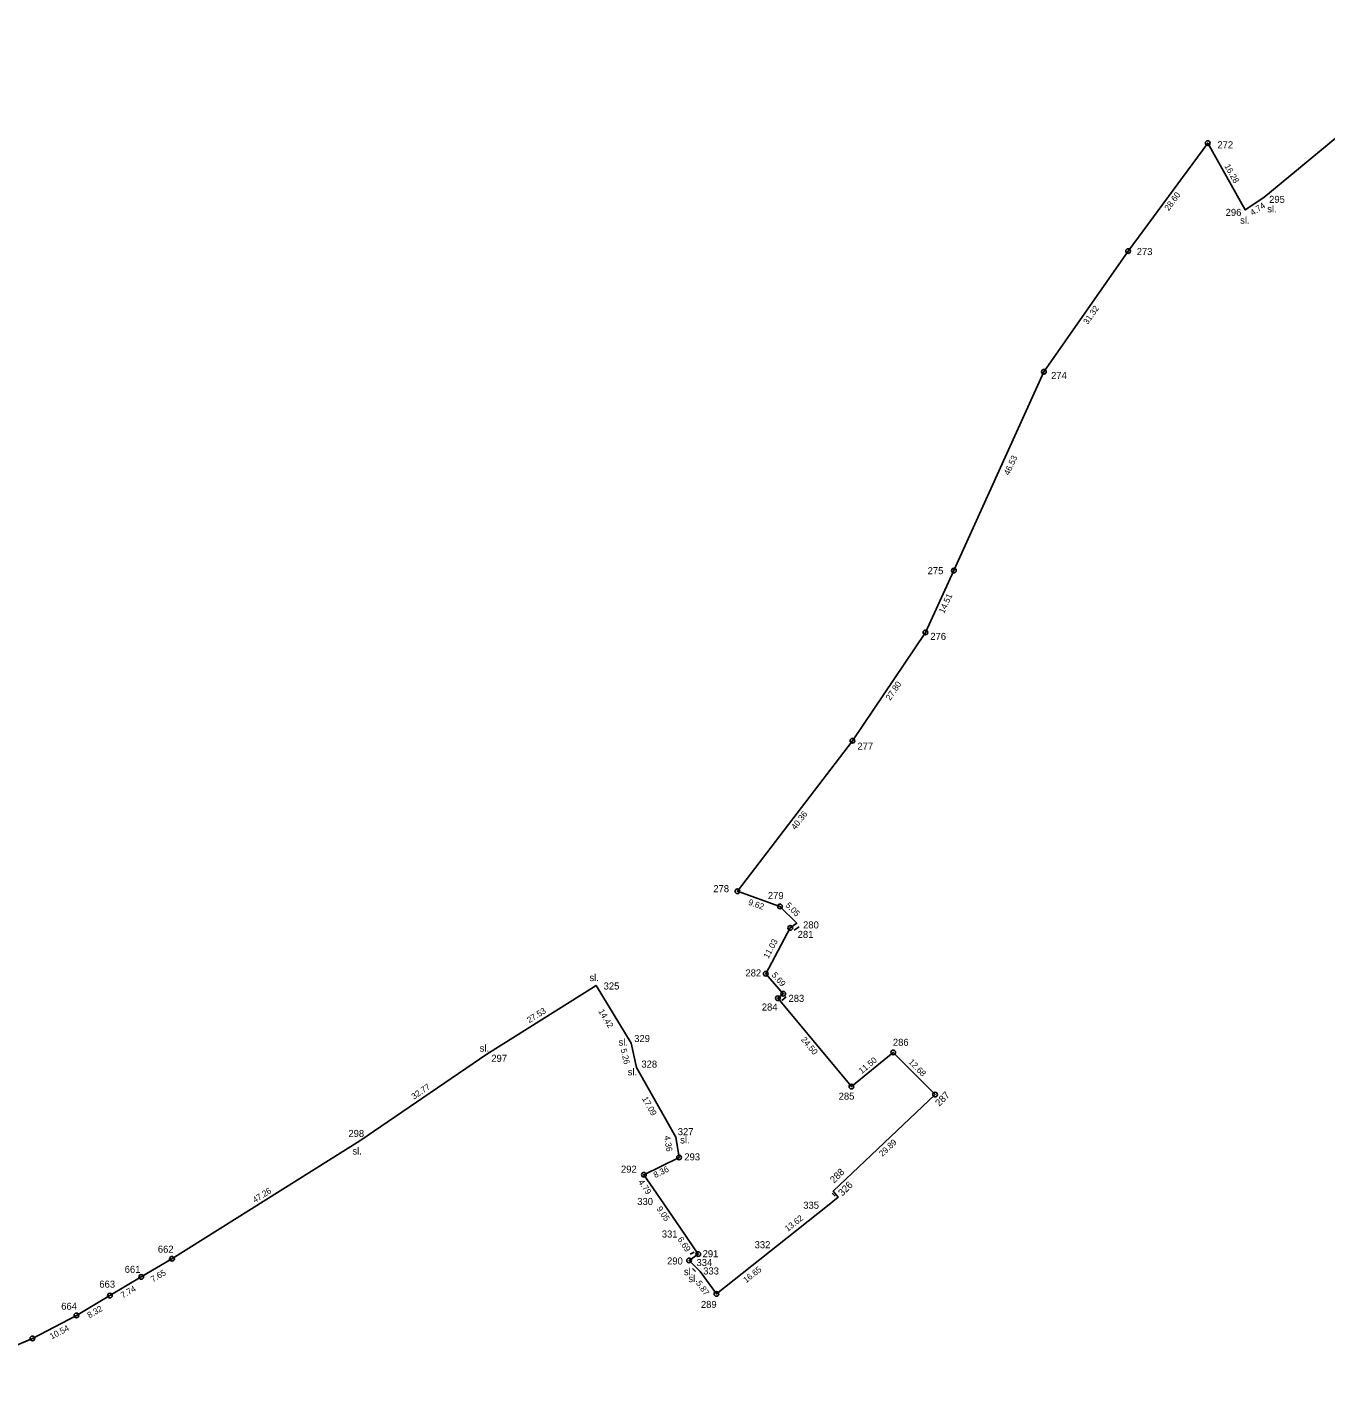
# Model space of a CAD drawing. Extents: x -555170 to -550532, y -1039598 to -1034701.
# Drawn here: x -552843.1 to -552566.7, y -1036461.5 to -1036169.1 of the extents above; entities that cross this region are included whole.
import ezdxf

# ---------------------------------------------------------------- set-up
doc = ezdxf.new("R2010")
doc.units = 0
for name, color, linetype in [('Vrstva 10', 7, 'Continuous'), ('Vrstva 40', 7, 'Continuous'), ('Vrstva 43', 7, 'Continuous'), ('Vrstva 48', 7, 'Continuous')]:
    doc.layers.add(name, color=color, linetype=linetype)

msp = doc.modelspace()

# ---------------------------------------------------------------- linework, layer by layer
at = {"layer": 'Vrstva 10'}
for p, q in [((-552678.77, -1036360.61), (-552679.86, -1036361.33)), ((-552681.54, -1036375.48), (-552682.47, -1036376.29)), ((-552671.7, -1036417.28), (-552671.1, -1036417.97)), ((-552701.13, -1036429.85), (-552701.97, -1036430.33)), ((-552701.46, -1036433.34), (-552700.87, -1036433.98))]:
    msp.add_line(p, q, dxfattribs=at)
at = {"layer": 'Vrstva 40'}
for p, q in [((-552536.04, -1036169.05), (-552579.83, -1036205.24)), ((-552591.76, -1036193.67), (-552608.73, -1036216.69)), ((-552583.76, -1036207.89), (-552591.76, -1036193.67)), ((-552579.83, -1036205.24), (-552583.76, -1036207.89)), ((-552608.73, -1036216.69), (-552626.64, -1036242.39)), ((-552626.64, -1036242.39), (-552645.81, -1036284.73)), ((-552645.81, -1036284.73), (-552651.88, -1036297.9)), ((-552651.88, -1036297.9), (-552667.43, -1036320.97)), ((-552667.43, -1036320.97), (-552691.92, -1036352.99)), ((-552691.92, -1036352.99), (-552682.85, -1036356.23)), ((-552682.85, -1036356.23), (-552679.28, -1036359.81)), ((-552679.28, -1036359.81), (-552680.66, -1036360.83)), ((-552680.66, -1036360.83), (-552685.88, -1036370.57)), ((-552685.88, -1036370.57), (-552682.14, -1036374.83)), ((-552722.02, -1036373.06), (-552745.27, -1036387.73)), ((-552714.55, -1036385.39), (-552722.02, -1036373.06)), ((-552682.14, -1036374.83), (-552683.3, -1036375.79)), ((-552683.3, -1036375.79), (-552667.63, -1036394.6)), ((-552713.39, -1036390.54), (-552714.55, -1036385.39)), ((-552745.27, -1036387.73), (-552772.34, -1036406.2)), ((-552667.63, -1036394.6), (-552658.72, -1036387.33)), ((-552658.72, -1036387.33), (-552649.81, -1036396.32)), ((-552705.02, -1036405.4), (-552713.39, -1036390.54)), ((-552649.81, -1036396.32), (-552671.5, -1036416.87)), ((-552772.34, -1036406.2), (-552812.32, -1036431.28)), ((-552704.34, -1036409.71), (-552705.02, -1036405.4)), ((-552711.81, -1036413.38), (-552704.34, -1036409.71)), ((-552709.12, -1036417.31), (-552711.81, -1036413.38)), ((-552704.01, -1036424.78), (-552709.12, -1036417.31)), ((-552670.47, -1036418.18), (-552672.72, -1036420.04)), ((-552671.5, -1036416.87), (-552670.47, -1036418.18)), ((-552672.72, -1036420.04), (-552683.38, -1036428.48)), ((-552700.24, -1036430.29), (-552704.01, -1036424.78)), ((-552683.38, -1036428.48), (-552696.39, -1036438.78)), ((-552812.32, -1036431.28), (-552818.88, -1036435.16)), ((-552702.21, -1036431.64), (-552700.24, -1036430.29)), ((-552701.4, -1036432.44), (-552702.21, -1036431.64)), ((-552699.81, -1036434.01), (-552701.4, -1036432.44)), ((-552818.88, -1036435.16), (-552825.54, -1036439.11)), ((-552696.39, -1036438.78), (-552699.81, -1036434.01)), ((-552825.54, -1036439.11), (-552832.68, -1036443.35)), ((-552832.68, -1036443.35), (-552842.03, -1036448.23)), ((-552842.03, -1036448.23), (-552873.09, -1036461.47))]:
    msp.add_line(p, q, dxfattribs=at)
at = {"layer": 'Vrstva 43'}
for p, q in [((-552591.76, -1036193.67), (-552591.76, -1036193.67)), ((-552583.76, -1036207.89), (-552583.76, -1036207.89)), ((-552579.83, -1036205.24), (-552579.83, -1036205.24)), ((-552608.73, -1036216.69), (-552608.73, -1036216.69)), ((-552626.64, -1036242.39), (-552626.64, -1036242.39)), ((-552645.81, -1036284.73), (-552645.81, -1036284.73)), ((-552651.88, -1036297.9), (-552651.88, -1036297.9)), ((-552667.43, -1036320.97), (-552667.43, -1036320.97)), ((-552691.92, -1036352.99), (-552691.92, -1036352.99)), ((-552682.85, -1036356.23), (-552682.85, -1036356.23)), ((-552679.28, -1036359.81), (-552679.28, -1036359.81)), ((-552680.66, -1036360.83), (-552680.66, -1036360.83)), ((-552685.88, -1036370.57), (-552685.88, -1036370.57)), ((-552722.02, -1036373.06), (-552722.02, -1036373.06)), ((-552683.3, -1036375.79), (-552683.3, -1036375.79)), ((-552682.14, -1036374.83), (-552682.14, -1036374.83)), ((-552714.55, -1036385.39), (-552714.55, -1036385.39)), ((-552745.27, -1036387.73), (-552745.27, -1036387.73)), ((-552658.72, -1036387.33), (-552658.72, -1036387.33)), ((-552713.39, -1036390.54), (-552713.39, -1036390.54)), ((-552667.63, -1036394.6), (-552667.63, -1036394.6)), ((-552649.81, -1036396.32), (-552649.81, -1036396.32)), ((-552772.34, -1036406.2), (-552772.34, -1036406.2)), ((-552705.02, -1036405.4), (-552705.02, -1036405.4)), ((-552704.34, -1036409.71), (-552704.34, -1036409.71)), ((-552711.81, -1036413.38), (-552711.81, -1036413.38)), ((-552709.12, -1036417.31), (-552709.12, -1036417.31)), ((-552671.5, -1036416.87), (-552671.5, -1036416.87)), ((-552670.47, -1036418.18), (-552670.47, -1036418.18)), ((-552672.72, -1036420.04), (-552672.72, -1036420.04)), ((-552704.01, -1036424.78), (-552704.01, -1036424.78)), ((-552683.38, -1036428.48), (-552683.38, -1036428.48)), ((-552812.32, -1036431.28), (-552812.32, -1036431.28)), ((-552702.21, -1036431.64), (-552702.21, -1036431.64)), ((-552701.4, -1036432.44), (-552701.4, -1036432.44)), ((-552700.24, -1036430.29), (-552700.24, -1036430.29)), ((-552818.88, -1036435.16), (-552818.88, -1036435.16)), ((-552699.81, -1036434.01), (-552699.81, -1036434.01)), ((-552696.39, -1036438.78), (-552696.39, -1036438.78)), ((-552825.54, -1036439.11), (-552825.54, -1036439.11)), ((-552832.68, -1036443.35), (-552832.68, -1036443.35)), ((-552842.03, -1036448.23), (-552842.03, -1036448.23))]:
    msp.add_line(p, q, dxfattribs=at)
for centre, radius in [((-552591.76, -1036193.67), 0.5), ((-552591.76, -1036193.67), 0.01), ((-552608.73, -1036216.69), 0.5), ((-552608.73, -1036216.69), 0.01), ((-552626.64, -1036242.39), 0.5), ((-552626.64, -1036242.39), 0.01), ((-552645.81, -1036284.73), 0.5), ((-552645.81, -1036284.73), 0.01), ((-552651.88, -1036297.9), 0.5), ((-552651.88, -1036297.9), 0.01), ((-552667.43, -1036320.97), 0.5), ((-552667.43, -1036320.97), 0.01), ((-552691.92, -1036353), 0.5), ((-552691.92, -1036353), 0.01), ((-552682.85, -1036356.23), 0.5), ((-552682.85, -1036356.23), 0.01), ((-552680.66, -1036360.83), 0.5), ((-552680.66, -1036360.83), 0.01), ((-552685.88, -1036370.57), 0.5), ((-552685.88, -1036370.57), 0.01), ((-552682.14, -1036374.83), 0.5), ((-552683.3, -1036375.79), 0.5), ((-552683.3, -1036375.79), 0.01), ((-552682.14, -1036374.83), 0.01), ((-552658.72, -1036387.33), 0.5), ((-552658.72, -1036387.33), 0.01), ((-552667.63, -1036394.6), 0.5), ((-552667.63, -1036394.6), 0.01), ((-552649.81, -1036396.32), 0.5), ((-552649.81, -1036396.32), 0.01), ((-552704.34, -1036409.71), 0.5), ((-552704.34, -1036409.71), 0.01), ((-552711.81, -1036413.38), 0.5), ((-552711.81, -1036413.38), 0.01), ((-552700.24, -1036430.29), 0.5), ((-552812.32, -1036431.28), 0.5), ((-552812.32, -1036431.28), 0.01), ((-552702.21, -1036431.64), 0.5), ((-552702.21, -1036431.64), 0.01), ((-552700.24, -1036430.29), 0.01), ((-552818.88, -1036435.16), 0.5), ((-552818.88, -1036435.16), 0.01), ((-552825.54, -1036439.11), 0.5), ((-552696.39, -1036438.78), 0.5), ((-552696.39, -1036438.78), 0.01), ((-552825.54, -1036439.11), 0.01), ((-552832.68, -1036443.35), 0.5), ((-552832.68, -1036443.35), 0.01), ((-552842.03, -1036448.24), 0.5), ((-552842.03, -1036448.24), 0.01)]:
    msp.add_circle(centre, radius, dxfattribs=at)
at = {"layer": 'Vrstva 48'}
msp.add_lwpolyline([(-552873.09, -1036461.47), (-552842.03, -1036448.23), (-552832.68, -1036443.35), (-552825.54, -1036439.11), (-552818.88, -1036435.16), (-552812.32, -1036431.28), (-552772.34, -1036406.2), (-552745.27, -1036387.73), (-552722.02, -1036373.06), (-552714.55, -1036385.39), (-552713.39, -1036390.54), (-552705.02, -1036405.4), (-552704.34, -1036409.71), (-552711.81, -1036413.38), (-552709.12, -1036417.31), (-552704.01, -1036424.78), (-552700.24, -1036430.29), (-552702.21, -1036431.64), (-552701.4, -1036432.44), (-552699.81, -1036434.01), (-552696.39, -1036438.78), (-552683.38, -1036428.48), (-552672.72, -1036420.04), (-552670.47, -1036418.18), (-552671.5, -1036416.87), (-552649.81, -1036396.32), (-552658.72, -1036387.33), (-552667.63, -1036394.6), (-552683.3, -1036375.79), (-552682.14, -1036374.83), (-552685.88, -1036370.57), (-552680.66, -1036360.83), (-552679.28, -1036359.81), (-552682.85, -1036356.23), (-552691.92, -1036352.99), (-552667.43, -1036320.97), (-552651.88, -1036297.9), (-552645.81, -1036284.73), (-552626.64, -1036242.39), (-552608.73, -1036216.69), (-552591.76, -1036193.67), (-552583.76, -1036207.89), (-552579.83, -1036205.24), (-552536.04, -1036169.05)], dxfattribs=at)

# ---------------------------------------------------------------- texts
at = {"layer": 'Vrstva 10'}
for s, rotation, p in [('16.28', 299.3492, (-552588.25, -1036198.58)), ('28.60', 53.5984, (-552600.06, -1036208.21)), ('4.74', 33.9918, (-552582.18, -1036209.18)), ('31.32', 55.1279, (-552617.32, -1036232.43)), ('46.53', 65.6407, (-552634.05, -1036264.53)), ('14.51', 65.2635, (-552647.91, -1036293.94)), ('27.80', 56.0129, (-552659.36, -1036312.48)), ('40.36', 52.595, (-552679.55, -1036340.03)), ('9.62', 340.3466, (-552689.71, -1036355.85)), ('5.05', 314.9823, (-552681.79, -1036356.13)), ('11.03', 61.8116, (-552685.32, -1036367.46)), ('5.69', 311.2884, (-552684.71, -1036370.92)), ('27.53', 32.2506, (-552736.21, -1036381.13)), ('14.42', 301.2091, (-552721.58, -1036378.58)), ('24.50', 309.8056, (-552678.46, -1036384.64)), ('5.26', 282.6936, (-552716.79, -1036386.66)), ('11.50', 39.2126, (-552665.43, -1036391.97)), ('12.68', 314.7451, (-552655.59, -1036389.5)), ('32.77', 34.3059, (-552760.79, -1036397.42)), ('17.09', 299.3907, (-552712.27, -1036397.18)), ('4.36', 278.9658, (-552707.53, -1036405.18)), ('29.89', 43.4647, (-552661.02, -1036409.62)), ('8.36', 26.1806, (-552709.41, -1036414.12)), ('4.79', 304.3748, (-552713.09, -1036414.96)), ('47.26', 32.1006, (-552794.68, -1036419.45)), ('9.05', 304.3748, (-552709.19, -1036420.66)), ('13.62', 38.3702, (-552681.18, -1036425.57)), ('6.69', 304.3748, (-552704.74, -1036427.16)), ('16.65', 38.3702, (-552690.05, -1036436.51)), ('7.65', 30.6028, (-552816.37, -1036436.34)), ('5.87', 305.6154, (-552700.8, -1036436.52)), ('7.74', 30.7195, (-552822.78, -1036439.75)), ('8.32', 30.6369, (-552829.89, -1036444)), ('10.54', 27.6096, (-552837.94, -1036448.49))]:
    msp.add_text(s, height=1.3, rotation=rotation, dxfattribs=at).set_placement(p)
at = {"layer": 'Vrstva 43'}
for s, p in [('272', (-552589.69, -1036194.78)), ('295', (-552578.68, -1036206.41)), ('296', (-552587.94, -1036209.18)), ('sl.', (-552579.08, -1036208.43)), ('sl.', (-552584.85, -1036210.84)), ('273', (-552606.88, -1036217.53)), ('274', (-552625.11, -1036243.91)), ('275', (-552651.4, -1036285.49)), ('276', (-552650.83, -1036299.48)), ('277', (-552666.36, -1036322.87)), ('278', (-552697.04, -1036353.21)), ('279', (-552685.43, -1036354.68)), ('280', (-552677.93, -1036360.93)), ('281', (-552679.08, -1036362.95)), ('sl.', (-552723.42, -1036372.15)), ('282', (-552690.2, -1036371.16)), ('325', (-552720.4, -1036373.94)), ('284', (-552686.72, -1036378.42)), ('283', (-552681.03, -1036376.57)), ('sl.', (-552746.79, -1036387.18)), ('sl.', (-552717.23, -1036385.9)), ('329', (-552713.89, -1036385.12)), ('286', (-552658.8, -1036385.93)), ('297', (-552744.32, -1036389.34)), ('328', (-552712.36, -1036390.57)), ('sl.', (-552715.27, -1036392.23)), ('285', (-552670.35, -1036397.4)), ('298', (-552774.75, -1036405.34)), ('327', (-552704.61, -1036404.96)), ('sl.', (-552704.1, -1036406.72)), ('sl.', (-552773.89, -1036409.08)), ('293', (-552703.21, -1036410.33)), ('292', (-552716.71, -1036412.95)), ('330', (-552713.24, -1036419.82)), ('335', (-552677.89, -1036420.63)), ('331', (-552708.01, -1036426.76)), ('662', (-552815.33, -1036429.99)), ('291', (-552699.32, -1036430.96)), ('332', (-552688.24, -1036429.04)), ('661', (-552822.39, -1036434.28)), ('290', (-552706.89, -1036432.5)), ('334', (-552700.63, -1036432.83)), ('333', (-552699.2, -1036434.63)), ('663', (-552827.79, -1036437.44)), ('sl.', (-552703.3, -1036434.78)), ('sl.', (-552702.35, -1036436.26)), ('664', (-552835.91, -1036442.14)), ('289', (-552699.68, -1036441.75))]:
    msp.add_text(s, height=1.5, dxfattribs=at).set_placement(p)
for s, p in [('287', (-552648.93, -1036398.93)), ('288', (-552671.33, -1036415.3)), ('326', (-552669.57, -1036418.06))]:
    msp.add_text(s, height=1.5, rotation=45, dxfattribs=at).set_placement(p)

doc.saveas('drawing.dxf')
